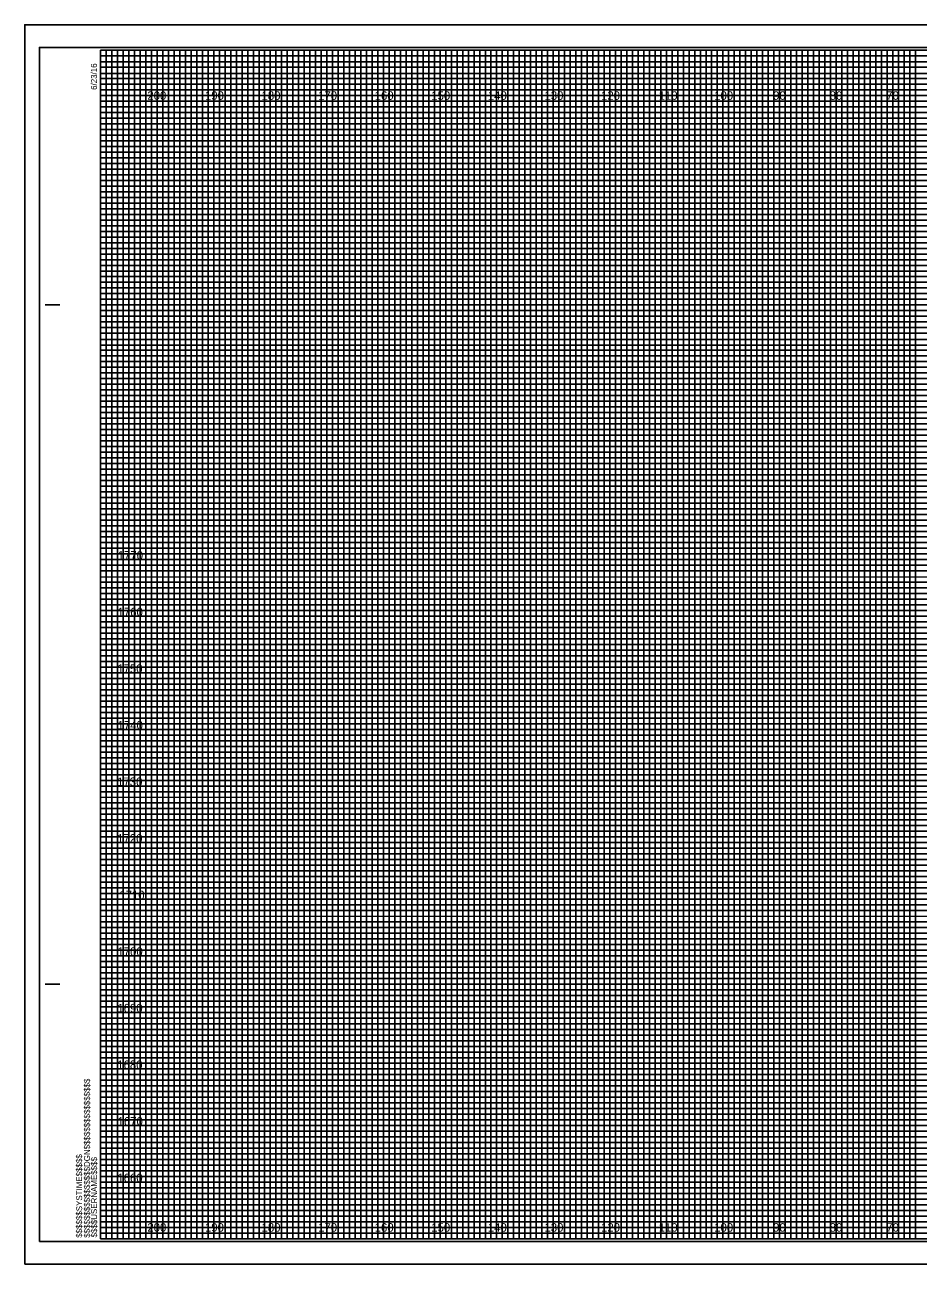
# Model space of a CAD drawing. Extents: x -419 to 4739, y -630 to 13534.
# Drawn here: x 2640.9 to 2798.8, y -25.9 to 193.1 of the extents above; entities that cross this region are included whole.
import ezdxf

# ---------------------------------------------------------------- set-up
doc = ezdxf.new("R2010")
doc.units = 0
for name, color, linetype in [('Old_Level_62', 7, 'Continuous'), ('Pattern 1', 7, 'Continuous'), ('Pattern 18', 7, 'Continuous'), ('Pattern 4', 7, 'Continuous'), ('Pattern 5', 7, 'Continuous'), ('Prop Dimension', 7, 'Continuous'), ('Prop Horizontal Alignment', 7, 'Continuous'), ('Raster_Level_0', 7, 'Continuous'), ('Scratch_Level_0', 7, 'Continuous'), ('Scratch_Level_3', 7, 'Continuous'), ('Scratch_Level_5', 7, 'Continuous')]:
    doc.layers.add(name, color=color, linetype=linetype)

msp = doc.modelspace()

# ---------------------------------------------------------------- linework, layer by layer
at = {"layer": 'Old_Level_62'}
for p, q in [((2644.45, 143.59), (2646.95, 143.59)), ((2644.55, 143.59), (2647.05, 143.59)), ((2644.45, 23.59), (2646.95, 23.59)), ((2644.55, 23.59), (2647.05, 23.59)), ((2654.25, -21.41), (2654.25, -21.41)), ((2654.25, -21.41), (2654.25, -21.41)), ((2654.25, -21.41), (2654.25, -21.41)), ((2654.25, -21.41), (2654.25, -21.41)), ((2654.25, -21.41), (2654.25, -21.41)), ((2654.25, -21.41), (2654.25, -21.41)), ((2654.25, -21.41), (2654.25, -21.41))]:
    msp.add_line(p, q, dxfattribs=at)
msp.add_lwpolyline([(2974.25, 188.59), (2654.25, 188.59), (2654.25, -21.41), (2974.25, -21.41)], close=True, dxfattribs=at)
at = {"layer": 'Pattern 18'}
msp.add_lwpolyline([(2640.85, -25.91), (2977.55, -25.91), (2977.55, 193.09), (2640.85, 193.09)], close=True, dxfattribs=at)
at = {"layer": 'Pattern 4'}
for p, q in [((2654.25, 187.59), (2914.25, 187.59)), ((2914.25, 186.57), (2654.25, 186.57)), ((2654.25, 186.57), (2654.25, 185.59)), ((2654.25, 185.59), (2914.25, 185.59)), ((2914.25, 184.48), (2654.25, 184.48)), ((2654.25, 184.48), (2654.25, 182.59)), ((2654.25, 182.59), (2974.25, 182.59))]:
    msp.add_line(p, q, dxfattribs=at)
for points in [[(2654.25, 181.59), (2924.25, 181.59), (2974.25, 181.59), (2974.25, 180.59), (2654.25, 180.59)], [(2654.25, 179.59), (2974.25, 179.59), (2974.25, 177.59), (2654.25, 177.59)], [(2654.25, 176.59), (2974.25, 176.59), (2974.25, 175.59), (2654.25, 175.57)], [(2654.25, 174.59), (2974.25, 174.59), (2974.25, 172.59), (2654.25, 172.59)], [(2654.25, 171.59), (2974.25, 171.59), (2974.25, 170.59), (2654.25, 170.59)], [(2654.25, 169.59), (2974.25, 169.59), (2974.25, 167.59), (2654.25, 167.59)], [(2654.25, 166.59), (2974.25, 166.59), (2974.25, 165.59), (2654.25, 165.59)], [(2654.25, 164.59), (2974.25, 164.59), (2974.25, 162.59), (2654.25, 162.59)], [(2654.25, 161.59), (2974.25, 161.59), (2974.25, 160.59), (2654.25, 160.59)], [(2654.25, 159.59), (2974.25, 159.59), (2974.25, 157.59), (2654.25, 157.59)], [(2654.25, 156.59), (2974.25, 156.59), (2974.25, 155.59), (2654.25, 155.59)], [(2654.25, 154.59), (2974.25, 154.59), (2974.25, 152.54), (2974.25, 151.59), (2974.25, 150.59), (2654.25, 150.59)], [(2654.25, 152.59), (2974.25, 152.59), (2974.25, 151.59), (2654.25, 151.59)], [(2654.25, 149.59), (2974.25, 149.59), (2974.25, 147.59), (2654.25, 147.62)], [(2654.25, 147.62), (2974.25, 147.59), (2974.25, 146.59), (2654.25, 146.59)], [(2654.25, 145.59), (2974.25, 145.59), (2974.25, 144.59), (2654.25, 144.59)], [(2654.25, 142.59), (2974.25, 142.59), (2974.25, 141.59), (2654.25, 141.59)], [(2654.25, 140.59), (2974.25, 140.59), (2974.25, 139.59), (2654.25, 139.59)], [(2654.18, 137.48), (2974.25, 137.48), (2974.25, 136.47), (2654.18, 136.47)], [(2654.25, 135.59), (2974.25, 135.59), (2974.25, 134.59), (2654.25, 134.59)], [(2654.25, 132.59), (2974.25, 132.59), (2974.25, 131.59), (2654.25, 131.59)], [(2654.25, 130.59), (2974.25, 130.59), (2974.25, 129.59), (2654.25, 129.59)], [(2654.25, 127.59), (2974.25, 127.59), (2974.25, 126.59), (2654.25, 126.59)], [(2654.25, 125.59), (2974.25, 125.59), (2974.25, 124.59), (2654.25, 124.59)], [(2654.25, 122.59), (2974.25, 122.59), (2974.25, 121.59), (2654.25, 121.59)], [(2654.25, 120.59), (2974.25, 120.59), (2974.25, 119.59), (2654.25, 119.59)], [(2654.25, 117.59), (2974.25, 117.59), (2974.24, 116.57), (2654.25, 116.59)], [(2654.25, 115.59), (2974.25, 115.59), (2974.25, 114.59), (2654.25, 114.59)], [(2654.25, 112.59), (2974.25, 112.59), (2974.25, 111.59), (2654.25, 111.59)], [(2654.25, 110.59), (2974.25, 110.59), (2974.25, 109.59), (2654.25, 109.59)], [(2654.25, 107.59), (2974.25, 107.59), (2974.25, 106.59), (2654.25, 106.59)], [(2654.25, 105.59), (2974.25, 105.59), (2974.25, 104.59), (2654.25, 104.59)], [(2654.25, 102.59), (2974.25, 102.59), (2974.25, 101.59), (2654.25, 101.59)], [(2654.25, 100.59), (2974.25, 100.59), (2974.25, 99.59), (2654.25, 99.59)], [(2654.25, 97.59), (2974.25, 97.59), (2974.25, 96.59), (2654.25, 96.59)], [(2654.25, 95.58), (2974.32, 95.5), (2974.25, 94.59), (2654.25, 94.59)], [(2654.25, 92.59), (2974.25, 92.59), (2974.25, 91.59), (2654.25, 91.59)], [(2654.25, 90.59), (2974.25, 90.59), (2974.25, 89.59), (2654.25, 89.59)], [(2654.25, 87.59), (2974.25, 87.59), (2974.25, 86.59), (2654.25, 86.59)], [(2654.25, 85.59), (2974.25, 85.59), (2974.25, 84.59), (2654.25, 84.59)], [(2654.25, 82.59), (2974.25, 82.59), (2974.25, 81.59), (2654.25, 81.59)], [(2654.25, 80.59), (2974.25, 80.59), (2974.25, 79.59), (2654.25, 79.59)], [(2654.25, 77.59), (2974.25, 77.59), (2974.25, 76.59), (2654.25, 76.59)], [(2654.25, 75.59), (2974.25, 75.59), (2974.25, 74.59), (2654.25, 74.59)], [(2654.25, 72.59), (2974.25, 72.59), (2974.25, 71.59), (2654.25, 71.59)], [(2654.25, 70.59), (2974.25, 70.59), (2974.25, 69.59), (2654.25, 69.59)], [(2654.25, 67.59), (2974.25, 67.59), (2974.25, 66.59), (2654.25, 66.59)], [(2654.25, 65.59), (2974.25, 65.59), (2974.25, 64.59), (2654.25, 64.59)], [(2654.25, 62.59), (2974.25, 62.59), (2974.25, 61.59), (2654.25, 61.59)], [(2654.25, 60.59), (2974.25, 60.59), (2974.25, 59.59), (2654.25, 59.59)], [(2654.25, 57.59), (2974.25, 57.59), (2974.24, 56.57), (2654.25, 56.59)], [(2654.25, 55.59), (2974.25, 55.59), (2974.25, 54.59), (2654.25, 54.59)], [(2654.25, 52.59), (2974.25, 52.59), (2974.25, 51.59), (2654.25, 51.59)], [(2654.25, 50.59), (2974.25, 50.59), (2974.25, 49.59), (2654.25, 49.59)], [(2654.25, 47.59), (2974.25, 47.59), (2974.25, 46.59), (2654.25, 46.59)], [(2654.25, 45.59), (2974.25, 45.59), (2974.25, 44.59), (2654.25, 44.59)], [(2654.25, 42.59), (2974.25, 42.59), (2974.25, 41.59), (2654.25, 41.59)], [(2654.25, 40.59), (2974.25, 40.59), (2974.25, 39.59), (2654.25, 39.59)], [(2654.25, 37.59), (2974.25, 37.59), (2974.25, 36.59), (2654.25, 36.59)], [(2654.25, 35.58), (2974.32, 35.5), (2974.25, 34.59), (2654.25, 34.59)], [(2654.25, 32.59), (2974.25, 32.59), (2974.25, 31.59), (2654.25, 31.59)], [(2654.25, 30.59), (2974.25, 30.59), (2974.25, 29.59), (2654.25, 29.59)], [(2654.25, 27.59), (2974.25, 27.59), (2974.25, 26.59), (2654.25, 26.59)], [(2654.25, 25.59), (2974.25, 25.59), (2974.25, 24.59), (2654.25, 24.59)], [(2654.25, 22.59), (2974.25, 22.59), (2974.25, 21.59), (2654.25, 21.59)], [(2654.25, 20.59), (2974.25, 20.59), (2974.25, 19.59), (2654.25, 19.59)], [(2654.25, 17.59), (2974.25, 17.59), (2974.25, 16.59), (2654.25, 16.59)], [(2654.25, 15.59), (2974.25, 15.59), (2974.25, 14.59), (2654.25, 14.59)], [(2654.25, 12.59), (2974.25, 12.59), (2974.25, 11.59), (2654.25, 11.59)], [(2654.25, 10.59), (2974.25, 10.59), (2974.25, 9.59), (2654.25, 9.59)], [(2654.25, 7.59), (2974.25, 7.59), (2974.25, 6.59), (2654.25, 6.59)], [(2654.25, 5.59), (2974.25, 5.59), (2974.25, 4.59), (2654.25, 4.59)], [(2654.25, 2.59), (2974.25, 2.59), (2974.25, 1.59), (2654.25, 1.59)], [(2654.25, 0.59), (2974.25, 0.59), (2974.25, -0.41), (2654.25, -0.41)], [(2654.25, -2.41), (2974.25, -2.41), (2974.25, -3.41), (2654.25, -3.41)], [(2654.25, -4.41), (2974.25, -4.41), (2974.25, -5.41), (2654.25, -5.41)], [(2654.25, -7.41), (2974.25, -7.41), (2974.25, -8.41), (2654.25, -8.41)], [(2654.25, -9.41), (2974.25, -9.41), (2974.25, -10.41), (2654.25, -10.41)], [(2654.25, -12.41), (2974.25, -12.41), (2974.25, -13.41), (2654.25, -13.41)], [(2654.25, -14.41), (2974.25, -14.41), (2974.25, -15.41), (2654.25, -15.41)], [(2654.25, -17.41), (2974.25, -17.41), (2974.25, -18.41), (2654.25, -18.41)], [(2654.25, -19.41), (2974.25, -19.41), (2974.25, -20.41), (2654.25, -20.41)]]:
    msp.add_lwpolyline(points, dxfattribs=at)
at = {"layer": 'Pattern 5'}
for p, q in [((2977.55, 193.09), (2640.85, 193.09)), ((2640.85, 193.09), (2640.85, -25.91)), ((2640.85, -25.91), (2977.55, -25.91))]:
    msp.add_line(p, q, dxfattribs=at)
at = {"layer": 'Prop Dimension'}
for points in [[(2654.25, -21.41), (2655.25, -21.41), (2655.25, 188.59), (2656.25, 188.59), (2656.25, -21.41)], [(2656.25, -21.41), (2657.25, -21.41), (2657.25, 188.59), (2658.25, 188.59), (2658.25, -21.41)], [(2659.25, -21.41), (2660.25, -21.41), (2660.25, 188.59), (2661.25, 188.59), (2661.25, -21.41)], [(2661.25, -21.41), (2662.25, -21.41), (2662.25, 188.59), (2663.25, 188.59), (2663.25, -21.41)], [(2664.25, -21.41), (2665.25, -21.41), (2665.25, 188.59), (2666.25, 188.59), (2666.25, -21.41)], [(2666.25, -21.41), (2667.25, -21.41), (2667.25, 188.59), (2668.25, 188.59), (2668.25, -21.41)], [(2669.25, -21.41), (2670.25, -21.41), (2670.25, 188.59), (2671.25, 188.59), (2671.25, -21.41)], [(2671.25, -21.41), (2672.25, -21.41), (2672.25, 188.59), (2673.25, 188.59), (2673.25, -21.41)], [(2674.25, -21.41), (2675.25, -21.41), (2675.25, 188.59), (2676.25, 188.59), (2676.25, -21.41)], [(2676.25, -21.41), (2677.25, -21.41), (2677.25, 188.59), (2678.25, 188.59), (2678.25, -21.41)], [(2679.25, -21.41), (2680.25, -21.41), (2680.25, 188.59), (2681.25, 188.59), (2681.25, -21.41)], [(2681.25, -21.41), (2682.25, -21.41), (2682.25, 188.59), (2683.25, 188.59), (2683.25, -21.41)], [(2684.25, -21.41), (2685.25, -21.41), (2685.25, 188.59), (2686.25, 188.59), (2686.25, -21.41)], [(2686.25, -21.41), (2687.25, -21.41), (2687.25, 188.59), (2688.25, 188.59), (2688.25, -21.41)], [(2689.25, -21.41), (2690.25, -21.41), (2690.25, 188.59), (2691.25, 188.59), (2691.25, -21.41)], [(2691.25, -21.41), (2692.25, -21.41), (2692.25, 188.59), (2693.25, 188.59), (2693.25, -21.41)], [(2694.25, -21.41), (2695.25, -21.41), (2695.25, 188.59), (2696.25, 188.59), (2696.25, -21.41)], [(2696.25, -21.41), (2697.25, -21.41), (2697.25, 188.59), (2698.25, 188.59), (2698.25, -21.41)], [(2699.25, -21.41), (2700.25, -21.41), (2700.25, 188.59), (2701.25, 188.59), (2701.25, -21.41)], [(2701.25, -21.41), (2702.25, -21.41), (2702.25, 188.59), (2703.25, 188.59), (2703.25, -21.41)], [(2704.25, -21.41), (2705.25, -21.41), (2705.25, 188.59), (2706.25, 188.59), (2706.25, -21.41)], [(2706.25, -21.41), (2707.25, -21.41), (2707.25, 188.59), (2708.25, 188.59), (2708.25, -21.41)], [(2709.25, -21.41), (2710.25, -21.41), (2710.25, 188.59), (2711.25, 188.59), (2711.25, -21.41)], [(2711.25, -21.41), (2712.25, -21.41), (2712.25, 188.59), (2713.25, 188.59), (2713.25, -21.41)], [(2714.25, -21.41), (2715.25, -21.41), (2715.25, 188.59), (2716.25, 188.59), (2716.25, -21.41)], [(2716.25, -21.41), (2717.25, -21.41), (2717.25, 188.59), (2718.25, 188.59), (2718.25, -21.41)], [(2719.25, -21.41), (2720.25, -21.41), (2720.25, 188.59), (2721.25, 188.59), (2721.25, -21.41)], [(2721.25, -21.41), (2722.25, -21.41), (2722.25, 188.59), (2723.25, 188.59), (2723.25, -21.41)], [(2724.25, -21.41), (2725.25, -21.41), (2725.25, 188.59), (2726.25, 188.59), (2726.25, -21.41)], [(2726.25, -21.41), (2727.25, -21.41), (2727.25, 188.59), (2728.25, 188.59), (2728.25, -21.41)], [(2729.25, -21.41), (2730.25, -21.41), (2730.25, 188.59), (2731.25, 188.59), (2731.25, -21.41)], [(2731.25, -21.41), (2732.25, -21.41), (2732.25, 188.59), (2733.25, 188.59), (2733.25, -21.41)], [(2734.25, -21.41), (2735.25, -21.41), (2735.25, 188.59), (2736.25, 188.59), (2736.25, -21.41)], [(2736.25, -21.41), (2737.25, -21.41), (2737.25, 188.59), (2738.25, 188.59), (2738.25, -21.41)], [(2739.25, -21.41), (2740.25, -21.41), (2740.25, 188.59), (2741.25, 188.59), (2741.25, -21.41)], [(2741.25, -21.41), (2742.25, -21.41), (2742.25, 188.59), (2743.25, 188.59), (2743.25, -21.41)], [(2744.25, -21.41), (2745.25, -21.41), (2745.25, 188.59), (2746.25, 188.59), (2746.25, -21.41)], [(2746.25, -21.41), (2747.25, -21.41), (2747.25, 188.59), (2748.25, 188.59), (2748.25, -21.41)], [(2749.25, -21.41), (2750.25, -21.41), (2750.25, 188.59), (2751.25, 188.59), (2751.25, -21.41)], [(2751.25, -21.41), (2752.25, -21.41), (2752.25, 188.59), (2753.25, 188.59), (2753.25, -21.41)], [(2754.25, -21.41), (2755.25, -21.41), (2755.25, 188.59), (2756.25, 188.59), (2756.25, -21.41)], [(2756.25, -21.41), (2757.25, -21.41), (2757.25, 188.59), (2758.25, 188.59), (2758.25, -21.41)], [(2759.25, -21.41), (2760.25, -21.41), (2760.25, 188.59), (2761.25, 188.59), (2761.25, -21.41)], [(2761.25, -21.41), (2762.25, -21.41), (2762.25, 188.59), (2763.25, 188.59), (2763.25, -21.41)], [(2764.25, -21.41), (2765.25, -21.41), (2765.25, 188.59), (2766.25, 188.59), (2766.25, -21.41)], [(2766.25, -21.41), (2767.25, -21.41), (2767.25, 188.59), (2768.25, 188.59), (2768.25, -21.41)], [(2769.25, -21.41), (2770.25, -21.41), (2770.25, 188.59), (2771.25, 188.59), (2771.25, -21.41)], [(2771.25, -21.41), (2772.25, -21.41), (2772.25, 188.59), (2773.25, 188.59), (2773.25, -21.41)], [(2774.25, -21.41), (2775.25, -21.41), (2775.25, 188.59), (2776.25, 188.59), (2776.25, -21.41)], [(2776.25, -21.41), (2777.25, -21.41), (2777.25, 188.59), (2778.25, 188.59), (2778.25, -21.41)], [(2779.25, -21.41), (2780.25, -21.41), (2780.25, 188.59), (2781.25, 188.59), (2781.25, -21.41)], [(2781.25, -21.41), (2782.25, -21.41), (2782.25, 188.59), (2783.25, 188.59), (2783.25, -21.41)], [(2784.25, -21.41), (2785.25, -21.41), (2785.25, 188.59), (2786.25, 188.59), (2786.25, -21.41)], [(2786.25, -21.41), (2787.25, -21.41), (2787.25, 188.59), (2788.25, 188.59), (2788.25, -21.41)], [(2789.25, -21.41), (2790.25, -21.41), (2790.25, 188.59), (2791.25, 188.59), (2791.25, -21.41)], [(2791.25, -21.41), (2792.25, -21.41), (2792.25, 188.59), (2793.25, 188.59), (2793.25, -21.41)], [(2794.25, -21.41), (2795.25, -21.41), (2795.25, 188.59), (2796.25, 188.59), (2796.25, -21.41)], [(2796.25, -21.41), (2797.25, -21.41), (2797.25, 188.59), (2798.25, 188.59), (2798.25, -21.41)]]:
    msp.add_lwpolyline(points, dxfattribs=at)
at = {"layer": 'Prop Horizontal Alignment'}
for points in [[(2654.25, 188.59), (2659.25, 188.59), (2659.25, -21.41), (2669.25, -21.41), (2669.25, 188.59), (2679.25, 188.59), (2679.25, -21.41), (2689.25, -21.41), (2689.25, 188.59), (2699.25, 188.59), (2699.25, -21.41), (2709.25, -21.41), (2709.25, 188.59), (2719.25, 188.59), (2719.25, -21.41), (2729.25, -21.41), (2729.25, 188.59), (2739.25, 188.59), (2739.25, -21.41), (2749.25, -21.41), (2749.25, 188.59), (2759.25, 188.59), (2759.25, -21.41), (2769.25, -21.41), (2769.25, 188.59), (2779.25, 188.59), (2779.25, -21.41), (2789.25, -21.41), (2789.25, 188.59), (2799.25, 188.59)], [(2654.25, 183.59), (2929.25, 183.59)], [(2654.25, 163.59), (2974.25, 163.59), (2974.25, 173.59), (2654.25, 173.59)], [(2654.25, 143.59), (2974.25, 143.59), (2974.25, 153.59), (2654.25, 153.59)], [(2654.25, 123.59), (2974.25, 123.59), (2974.25, 133.59), (2654.25, 133.59)], [(2654.25, 103.59), (2974.25, 103.59), (2974.25, 113.59), (2654.25, 113.59)], [(2654.25, 83.59), (2974.25, 83.59), (2974.25, 93.59), (2654.25, 93.59)], [(2654.25, 63.59), (2974.25, 63.59), (2974.25, 73.59), (2654.25, 73.59)], [(2654.25, 43.59), (2974.25, 43.59), (2974.25, 53.59), (2654.25, 53.59)], [(2654.25, 23.59), (2974.25, 23.59), (2974.25, 33.59), (2654.25, 33.59)], [(2654.25, 3.59), (2974.25, 3.59), (2974.25, 13.59), (2654.25, 13.59)], [(2654.25, -16.41), (2974.25, -16.41), (2974.25, -6.41), (2654.25, -6.41)]]:
    msp.add_lwpolyline(points, dxfattribs=at)
at = {"layer": 'Scratch_Level_0'}
for p, q in [((2664.25, -21.41), (2664.25, 188.59)), ((2674.25, -21.41), (2674.25, 188.59)), ((2684.25, -21.41), (2684.25, 188.59)), ((2694.25, -21.41), (2694.25, 188.59)), ((2704.25, -21.41), (2704.25, 188.59)), ((2714.25, -21.41), (2714.25, 188.59)), ((2724.25, -21.41), (2724.25, 188.59)), ((2734.25, -21.41), (2734.25, 188.59)), ((2744.25, -21.41), (2744.25, 188.59)), ((2754.25, -21.41), (2754.25, 188.59)), ((2764.25, -21.41), (2764.25, 188.59)), ((2774.25, -21.41), (2774.25, 188.59)), ((2784.25, -21.41), (2784.25, 188.59)), ((2794.25, -21.41), (2794.25, 188.59)), ((2654.25, 178.59), (2974.25, 178.59)), ((2654.25, 168.59), (2974.25, 168.59)), ((2654.25, 158.59), (2974.25, 158.59)), ((2654.25, 148.59), (2974.25, 148.59)), ((2654.25, 138.59), (2974.25, 138.59)), ((2654.25, 128.59), (2974.25, 128.59)), ((2654.25, 118.59), (2974.25, 118.59)), ((2654.25, 108.59), (2974.25, 108.59)), ((2654.25, 98.59), (2974.25, 98.59)), ((2654.25, 88.59), (2974.25, 88.59)), ((2654.25, 78.59), (2974.25, 78.59)), ((2654.25, 68.59), (2974.25, 68.59)), ((2654.25, 58.59), (2974.25, 58.59)), ((2654.25, 48.59), (2974.25, 48.59)), ((2654.25, 38.59), (2974.25, 38.59)), ((2654.25, 28.59), (2974.25, 28.59)), ((2654.25, 18.59), (2974.25, 18.59)), ((2654.25, 8.59), (2974.25, 8.59)), ((2654.25, -1.41), (2974.25, -1.41)), ((2654.25, -11.41), (2974.25, -11.41))]:
    msp.add_line(p, q, dxfattribs=at)
at = {"layer": 'Scratch_Level_3'}
for p, q in [((2664.25, 188.59), (2654.25, 188.59)), ((2664.25, -21.41), (2664.25, 188.59)), ((2684.25, 188.59), (2674.25, 188.59)), ((2674.25, 188.59), (2674.25, -21.41)), ((2684.25, -21.41), (2684.25, 188.59)), ((2704.25, 188.59), (2694.25, 188.59)), ((2694.25, 188.59), (2694.25, -21.41)), ((2704.25, -21.41), (2704.25, 188.59)), ((2724.25, 188.59), (2714.25, 188.59)), ((2714.25, 188.59), (2714.25, -21.41)), ((2724.25, -21.41), (2724.25, 188.59)), ((2744.25, 188.59), (2734.25, 188.59)), ((2734.25, 188.59), (2734.25, -21.41)), ((2744.25, -21.41), (2744.25, 188.59)), ((2764.25, 188.59), (2754.25, 188.59)), ((2754.25, 188.59), (2754.25, -21.41)), ((2764.25, -21.41), (2764.25, 188.59)), ((2784.25, 188.59), (2774.25, 188.59)), ((2774.25, 188.59), (2774.25, -21.41)), ((2784.25, -21.41), (2784.25, 188.59)), ((2804.25, 188.59), (2794.25, 188.59)), ((2794.25, 188.59), (2794.25, -21.41)), ((2674.25, -21.41), (2664.25, -21.41)), ((2694.25, -21.41), (2684.25, -21.41)), ((2714.25, -21.41), (2704.25, -21.41)), ((2734.25, -21.41), (2724.25, -21.41)), ((2754.25, -21.41), (2744.25, -21.41)), ((2774.25, -21.41), (2764.25, -21.41)), ((2794.25, -21.41), (2784.25, -21.41))]:
    msp.add_line(p, q, dxfattribs=at)
for points in [[(2654.25, 178.59), (2974.25, 178.59), (2974.25, 168.59), (2654.25, 168.59)], [(2654.25, 158.59), (2974.25, 158.59), (2974.25, 148.59), (2654.25, 148.59)], [(2654.25, 138.59), (2974.25, 138.59), (2974.25, 128.59), (2654.25, 128.59)], [(2654.25, 118.59), (2974.25, 118.59), (2974.25, 108.59), (2654.25, 108.59)], [(2654.25, 98.59), (2974.25, 98.59), (2974.25, 88.59), (2654.25, 88.59)], [(2654.25, 78.59), (2974.25, 78.59), (2974.25, 68.59), (2654.25, 68.59)], [(2654.25, 58.59), (2974.25, 58.59), (2974.25, 48.59), (2654.25, 48.59)], [(2654.25, 38.59), (2974.25, 38.59), (2974.25, 28.59), (2654.25, 28.59)], [(2654.25, 18.59), (2974.25, 18.59), (2974.25, 8.59), (2654.25, 8.59)], [(2654.25, -1.41), (2974.25, -1.41), (2974.25, -11.41), (2654.25, -11.41)]]:
    msp.add_lwpolyline(points, dxfattribs=at)
at = {"layer": 'Scratch_Level_5'}
msp.add_lwpolyline([(2643.45, -21.91), (2976.65, -21.91), (2976.65, 189.09), (2643.45, 189.09)], close=True, dxfattribs=at)

# ---------------------------------------------------------------- texts
at = {"layer": 'Old_Level_62'}
for s, p in [('6/23/16', (2653.6, 181.59)), ('$$$$$$$$$$$$$$$$DGN$$$$$$$$$$$$$$$$', (2652.37, -21.23)), ('$$$$$$SYSTIME$$$$$', (2650.99, -21.23)), ('$$$$USERNAME$$$$', (2653.63, -21.18))]:
    msp.add_text(s, height=1.05, rotation=90, dxfattribs=at).set_placement(p)
at = {"layer": 'Pattern 1'}
for s, p in [('1770', (2657.29, 98.59)), ('1760', (2657.26, 88.59)), ('1750', (2657.21, 78.59)), ('1740', (2657.26, 68.59)), ('1730', (2657.18, 58.59)), ('1720', (2657.19, 48.59)), ('1710', (2657.57, 38.59)), ('1700', (2657.23, 28.59)), ('1690', (2657.22, 18.59)), ('1680', (2657.2, 8.59)), ('1670', (2657.26, -1.41)), ('1660', (2657.22, -11.41))]:
    msp.add_text(s, height=1.5, dxfattribs=at).set_placement(p)
at = {"layer": 'Raster_Level_0'}
for s, p in [('200', (2662.52, 179.84)), ('190', (2672.7, 179.84)), ('180', (2682.7, 179.84)), ('170', (2692.7, 179.84)), ('160', (2702.7, 179.84)), ('150', (2712.7, 179.84)), ('140', (2722.7, 179.84)), ('130', (2732.7, 179.84)), ('120', (2742.7, 179.84)), ('110', (2752.88, 179.84)), ('100', (2762.7, 179.84)), ('90', (2773.11, 179.84)), ('80', (2783.11, 179.84)), ('70', (2793.11, 179.84)), ('200', (2662.52, -20.16)), ('190', (2672.7, -20.16)), ('180', (2682.7, -20.16)), ('170', (2692.7, -20.16)), ('160', (2702.7, -20.16)), ('150', (2712.7, -20.16)), ('140', (2722.7, -20.16)), ('130', (2732.7, -20.16)), ('120', (2742.7, -20.16)), ('110', (2752.88, -20.16)), ('100', (2762.7, -20.16)), ('90', (2773.11, -20.16)), ('80', (2783.11, -20.16)), ('70', (2793.11, -20.16))]:
    msp.add_text(s, height=1.5, dxfattribs=at).set_placement(p)

doc.saveas('drawing.dxf')
